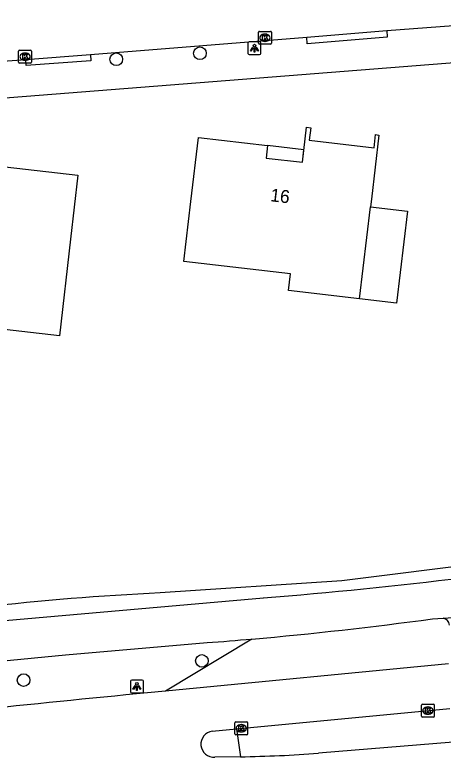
# Model space of a CAD drawing. Extents: x 162398 to 163643, y 386453 to 387397.
# Drawn here: x 163096.1 to 163129.2, y 386513 to 386570.4 of the extents above; entities that cross this region are included whole.
import ezdxf

# ---------------------------------------------------------------- set-up
doc = ezdxf.new("R2010")
doc.units = 0
for name, color, linetype in [('IMGEO_Berm_groen', 7, 'Continuous'), ('IMGEO_Boom', 7, 'Continuous'), ('IMGEO_Fietspad_gesloten', 7, 'Continuous'), ('IMGEO_Groenvoorziening', 7, 'Continuous'), ('IMGEO_Kolk', 7, 'Continuous'), ('IMGEO_Lichtpunt', 7, 'Continuous'), ('IMGEO_Muur', 7, 'Continuous'), ('IMGEO_Pand', 7, 'Continuous'), ('IMGEO_Pand_nummerreeks', 7, 'Continuous'), ('IMGEO_Pand_overbouw', 7, 'Continuous'), ('IMGEO_Rijbaan_lokaal_open', 7, 'Continuous'), ('IMGEO_Rijbaan_regionaal_gesloten', 7, 'Continuous'), ('IMGEO_Verkeerseiland_gesloten', 7, 'Continuous'), ('IMGEO_Voetpad_open', 7, 'Continuous')]:
    doc.layers.add(name, color=color, linetype=linetype)

msp = doc.modelspace()

# ---------------------------------------------------------------- linework, layer by layer
at = {"layer": 'IMGEO_Berm_groen'}
msp.add_lwpolyline([(163114.445, 386522.175), (163107.763, 386518.15)], dxfattribs=at)
at = {"layer": 'IMGEO_Boom'}
for centre in [(163110.437, 386567.457), (163103.966, 386566.988), (163110.583, 386520.488), (163096.797, 386518.996)]:
    msp.add_circle(centre, 0.489, dxfattribs=at)
at = {"layer": 'IMGEO_Fietspad_gesloten'}
for points in [[(163068.381, 386520.901), (163093.275, 386523.436), (163115.339, 386525.357)], [(163128.412, 386523.738), (163129.247, 386523.78)], [(163129.247, 386523.78), (163132.704, 386524.019), (163132.995, 386520.565)], [(163067.923, 386517.561), (163068.628, 386517.907), (163100.034, 386520.946), (163110.988, 386521.896)]]:
    msp.add_lwpolyline(points, dxfattribs=at)
for centre, radius, start, end in [((163086.566, 386887.267), 363.052, 274.54557, 277.00234), ((163089.879, 386804.881), 283.772, 274.96624, 277.80418), ((163090.814, 386793.421), 272.273, 274.24918, 274.97902)]:
    msp.add_arc(centre, radius, start, end, dxfattribs=at)
at = {"layer": 'IMGEO_Groenvoorziening'}
msp.add_lwpolyline([(163243.313, 386542.596), (163241.901, 386539.593), (163239.582, 386537.387), (163183.884, 386534.66), (163132.616, 386530.652), (163132.716, 386528.091), (163121.414, 386526.667), (163107.365, 386525.735)], dxfattribs=at)
msp.add_arc((163115.529, 386339.232), 186.681, 92.50635, 96.74894, dxfattribs=at)
at = {"layer": 'IMGEO_Kolk'}
for p, q in [((163114.965, 386568.225), (163114.965, 386569.077)), ((163115.04, 386569.151), (163115.892, 386569.151)), ((163115.966, 386569.077), (163115.966, 386568.225)), ((163115.453, 386568.931), (163115.478, 386568.931)), ((163115.892, 386568.151), (163115.04, 386568.151)), ((163115.476, 386568.371), (163115.451, 386568.371)), ((163096.409, 386566.77), (163096.409, 386567.622)), ((163096.484, 386567.696), (163097.336, 386567.696)), ((163096.897, 386567.476), (163096.922, 386567.476)), ((163097.41, 386567.622), (163097.41, 386566.77)), ((163097.336, 386566.696), (163096.484, 386566.696)), ((163096.92, 386566.916), (163096.895, 386566.916)), ((163127.563, 386516.218), (163127.563, 386517.07)), ((163127.638, 386517.144), (163128.49, 386517.144)), ((163128.051, 386516.924), (163128.076, 386516.924)), ((163128.564, 386517.07), (163128.564, 386516.218)), ((163128.074, 386516.364), (163128.049, 386516.364)), ((163113.126, 386514.851), (163113.126, 386515.703)), ((163113.201, 386515.777), (163114.053, 386515.777)), ((163114.127, 386515.703), (163114.127, 386514.851)), ((163128.49, 386516.144), (163127.638, 386516.144)), ((163113.614, 386515.557), (163113.639, 386515.557)), ((163114.053, 386514.777), (163113.201, 386514.777)), ((163113.637, 386514.997), (163113.612, 386514.997))]:
    msp.add_line(p, q, dxfattribs=at)
for points in [[(163114.965, 386568.225), (163114.965, 386569.077)], [(163115.04, 386569.151), (163115.892, 386569.151)], [(163115.966, 386569.077), (163115.966, 386568.225)], [(163115.286, 386568.851), (163115.409, 386568.851), (163115.409, 386568.7), (163115.539, 386568.851), (163115.703, 386568.851), (163115.557, 386568.7), (163115.71, 386568.451), (163115.558, 386568.451), (163115.473, 386568.615), (163115.409, 386568.548), (163115.409, 386568.451), (163115.286, 386568.451), (163115.286, 386568.851)], [(163115.892, 386568.151), (163115.04, 386568.151)], [(163096.409, 386566.77), (163096.409, 386567.622)], [(163096.484, 386567.696), (163097.336, 386567.696)], [(163096.73, 386567.396), (163096.853, 386567.396), (163096.853, 386567.245), (163096.983, 386567.396), (163097.147, 386567.396), (163097.001, 386567.245), (163097.154, 386566.996), (163097.002, 386566.996), (163096.917, 386567.16), (163096.853, 386567.093), (163096.853, 386566.996), (163096.73, 386566.996), (163096.73, 386567.396)], [(163097.41, 386567.622), (163097.41, 386566.77)], [(163097.336, 386566.696), (163096.484, 386566.696)], [(163127.563, 386516.218), (163127.563, 386517.07)], [(163127.638, 386517.144), (163128.49, 386517.144)], [(163127.884, 386516.844), (163128.007, 386516.844), (163128.007, 386516.693), (163128.137, 386516.844), (163128.301, 386516.844), (163128.155, 386516.693), (163128.308, 386516.444), (163128.156, 386516.444), (163128.071, 386516.608), (163128.007, 386516.541), (163128.007, 386516.444), (163127.884, 386516.444), (163127.884, 386516.844)], [(163128.564, 386517.07), (163128.564, 386516.218)], [(163113.126, 386514.851), (163113.126, 386515.703)], [(163113.201, 386515.777), (163114.053, 386515.777)], [(163114.127, 386515.703), (163114.127, 386514.851)], [(163128.49, 386516.144), (163127.638, 386516.144)], [(163113.447, 386515.477), (163113.57, 386515.477), (163113.57, 386515.326), (163113.7, 386515.477), (163113.864, 386515.477), (163113.718, 386515.326), (163113.871, 386515.077), (163113.719, 386515.077), (163113.634, 386515.241), (163113.57, 386515.174), (163113.57, 386515.077), (163113.447, 386515.077), (163113.447, 386515.477)], [(163114.053, 386514.777), (163113.201, 386514.777)]]:
    msp.add_lwpolyline(points, dxfattribs=at)
for centre, start, end in [((163115.042, 386569.075), 91.55205, 178.44795), ((163115.042, 386569.075), 91.55205, 178.44795), ((163115.89, 386569.075), 1.55205, 88.44795), ((163115.89, 386569.075), 1.55205, 88.44795), ((163115.042, 386568.227), 181.55205, 268.44795), ((163115.042, 386568.227), 181.55205, 268.44795), ((163115.89, 386568.227), 271.55205, 358.44795), ((163115.89, 386568.227), 271.55205, 358.44795), ((163096.486, 386567.62), 91.55205, 178.44795), ((163096.486, 386567.62), 91.55205, 178.44795), ((163097.334, 386567.62), 1.55205, 88.44795), ((163097.334, 386567.62), 1.55205, 88.44795), ((163096.486, 386566.772), 181.55205, 268.44795), ((163096.486, 386566.772), 181.55205, 268.44795), ((163097.334, 386566.772), 271.55205, 358.44795), ((163097.334, 386566.772), 271.55205, 358.44795), ((163127.64, 386517.068), 91.55205, 178.44795), ((163127.64, 386517.068), 91.55205, 178.44795), ((163128.488, 386517.068), 1.55205, 88.44795), ((163128.488, 386517.068), 1.55205, 88.44795), ((163127.64, 386516.22), 181.55205, 268.44795), ((163127.64, 386516.22), 181.55205, 268.44795), ((163128.488, 386516.22), 271.55205, 358.44795), ((163128.488, 386516.22), 271.55205, 358.44795), ((163113.203, 386515.701), 91.55205, 178.44795), ((163113.203, 386515.701), 91.55205, 178.44795), ((163114.051, 386515.701), 1.55205, 88.44795), ((163114.051, 386515.701), 1.55205, 88.44795), ((163113.203, 386514.853), 181.55205, 268.44795), ((163113.203, 386514.853), 181.55205, 268.44795), ((163114.051, 386514.853), 271.55205, 358.44795), ((163114.051, 386514.853), 271.55205, 358.44795)]:
    msp.add_arc(centre, 0.0765, start, end, dxfattribs=at)
for centre, major_axis, ratio, start_param, end_param in [((163115.452, 386568.651), (-0.387, 0.002), 0.722429, 4.712389, 7.853982), ((163115.477, 386568.651), (-0.39, 0.002), 0.717154, 1.570796, 4.712389), ((163096.896, 386567.196), (-0.387, 0.002), 0.722429, 4.712389, 7.853982), ((163096.921, 386567.196), (-0.39, 0.002), 0.717154, 1.570796, 4.712389), ((163128.05, 386516.644), (-0.387, 0.002), 0.722429, 4.712389, 7.853982), ((163128.075, 386516.644), (-0.39, 0.002), 0.717154, 1.570796, 4.712389), ((163113.613, 386515.277), (-0.387, 0.002), 0.722429, 4.712389, 7.853982), ((163113.638, 386515.277), (-0.39, 0.002), 0.717154, 1.570796, 4.712389)]:
    msp.add_ellipse(centre, major_axis=major_axis, ratio=ratio, start_param=start_param, end_param=end_param, dxfattribs=at)
at = {"layer": 'IMGEO_Lichtpunt'}
for p, q in [((163114.152, 386568.252), (163114.152, 386567.445)), ((163114.152, 386568.252), (163114.152, 386567.445)), ((163115.054, 386568.347), (163114.246, 386568.347)), ((163115.054, 386568.347), (163114.246, 386568.347)), ((163115.148, 386567.445), (163115.148, 386568.252)), ((163115.148, 386567.445), (163115.148, 386568.252)), ((163114.246, 386567.351), (163115.054, 386567.351)), ((163114.246, 386567.351), (163115.054, 386567.351)), ((163105.064, 386518.909), (163105.064, 386518.102)), ((163105.064, 386518.909), (163105.064, 386518.102)), ((163105.966, 386519.004), (163105.158, 386519.004)), ((163105.966, 386519.004), (163105.158, 386519.004)), ((163106.06, 386518.102), (163106.06, 386518.909)), ((163106.06, 386518.102), (163106.06, 386518.909)), ((163105.158, 386518.008), (163105.966, 386518.008)), ((163105.158, 386518.008), (163105.966, 386518.008))]:
    msp.add_line(p, q, dxfattribs=at)
for points in [[(163114.526, 386567.916), (163114.565, 386567.888), (163114.377, 386567.626), (163114.339, 386567.653), (163114.526, 386567.916)], [(163114.628, 386567.868), (163114.675, 386567.868), (163114.675, 386567.546), (163114.628, 386567.546), (163114.628, 386567.868)], [(163114.738, 386567.888), (163114.776, 386567.915), (163114.963, 386567.653), (163114.924, 386567.625), (163114.738, 386567.888)], [(163105.438, 386518.573), (163105.477, 386518.545), (163105.289, 386518.283), (163105.251, 386518.31), (163105.438, 386518.573)], [(163105.54, 386518.525), (163105.587, 386518.525), (163105.587, 386518.203), (163105.54, 386518.203), (163105.54, 386518.525)], [(163105.65, 386518.545), (163105.688, 386518.572), (163105.875, 386518.31), (163105.836, 386518.282), (163105.65, 386518.545)]]:
    msp.add_lwpolyline(points, dxfattribs=at)
for centre in [(163114.651, 386568.05), (163105.563, 386518.707)]:
    msp.add_circle(centre, 0.0994, dxfattribs=at)
for centre, start, end in [((163114.246, 386568.252), 90, 180), ((163114.246, 386568.252), 90, 180), ((163115.054, 386568.252), 0, 90), ((163115.054, 386568.252), 0, 90), ((163114.246, 386567.445), 180, 270), ((163114.246, 386567.445), 180, 270), ((163115.054, 386567.445), 270, 0), ((163115.054, 386567.445), 270, 360), ((163105.158, 386518.909), 90, 180), ((163105.158, 386518.909), 90, 180), ((163105.966, 386518.909), 0, 90), ((163105.966, 386518.909), 0, 90), ((163105.158, 386518.102), 180, 270), ((163105.158, 386518.102), 180, 270), ((163105.966, 386518.102), 270, 0), ((163105.966, 386518.102), 270, 360)]:
    msp.add_arc(centre, 0.0946, start, end, dxfattribs=at)
at = {"layer": 'IMGEO_Muur'}
msp.add_lwpolyline([(163243.313, 386542.596), (163241.901, 386539.593), (163239.582, 386537.387), (163183.884, 386534.66), (163132.616, 386530.652), (163132.716, 386528.091), (163121.414, 386526.667), (163107.365, 386525.735)], dxfattribs=at)
msp.add_arc((163115.529, 386339.232), 186.681, 92.50635, 96.74894, dxfattribs=at)
at = {"layer": 'IMGEO_Pand'}
for points in [[(163122.781, 386548.467), (163117.278, 386549.118), (163117.429, 386550.394), (163109.191, 386551.368), (163109.737, 386555.988), (163110.324, 386560.953), (163115.673, 386560.32), (163115.559, 386559.359), (163118.356, 386559.028), (163118.677, 386561.743), (163119.006, 386561.704), (163118.893, 386560.749), (163123.9, 386560.157), (163124.019, 386561.166), (163124.279, 386561.135), (163123.692, 386556.17), (163123.622, 386555.58)], [(163082.311, 386547.598), (163083.189, 386555.309), (163087.476, 386554.821), (163088.006, 386559.453), (163088.447, 386559.403), (163088.324, 386558.334), (163095.242, 386557.543), (163095.372, 386558.687), (163100.995, 386558.044), (163100.427, 386553.077), (163099.576, 386545.625), (163082.311, 386547.598)], [(163123.622, 386555.58), (163126.49, 386555.241), (163125.648, 386548.128), (163122.781, 386548.467)], [(163122.781, 386548.467), (163123.622, 386555.58)]]:
    msp.add_lwpolyline(points, dxfattribs=at)
at = {"layer": 'IMGEO_Pand_overbouw'}
msp.add_lwpolyline([(163118.469, 386559.989), (163115.673, 386560.32), (163115.559, 386559.359), (163118.356, 386559.028)], close=True, dxfattribs=at)
at = {"layer": 'IMGEO_Rijbaan_lokaal_open'}
for points in [[(163124.883, 386569.21), (163138.986, 386570.276), (163139.978, 386570.426)], [(163118.7, 386568.695), (163124.883, 386569.21)], [(163101.964, 386567.36), (163118.7, 386568.695)], [(163096.974, 386566.98), (163101.964, 386567.36)], [(163087.793, 386566.294), (163096.974, 386566.98)]]:
    msp.add_lwpolyline(points, dxfattribs=at)
at = {"layer": 'IMGEO_Rijbaan_regionaal_gesloten'}
for points in [[(163129.649, 386520.259), (163107.763, 386518.15)], [(163107.763, 386518.15), (163106.385, 386518.017)], [(163113.263, 386515.243), (163129.754, 386516.804)], [(163111.389, 386515.058), (163113.263, 386515.243)], [(163130.019, 386514.208), (163119.609, 386513.357)], [(163113.565, 386513.075), (163111.597, 386513.047)]]:
    msp.add_lwpolyline(points, dxfattribs=at)
for centre, radius, start, end in [((163222.591, 385306.317), 1217.26, 95.478115, 96.758428), ((163111.52, 386514.055), 1.011, 97.43383, 274.37651), ((163112.409, 386602.756), 89.688, 270.73834, 274.60438)]:
    msp.add_arc(centre, radius, start, end, dxfattribs=at)
at = {"layer": 'IMGEO_Verkeerseiland_gesloten'}
msp.add_lwpolyline([(163113.263, 386515.243), (163113.565, 386513.075)], dxfattribs=at)
at = {"layer": 'IMGEO_Voetpad_open'}
for points in [[(163124.883, 386569.21), (163124.919, 386568.712), (163118.736, 386568.197), (163118.7, 386568.695)], [(163139.616, 386567.455), (163000, 386556.492), (162997.872, 386556.325)], [(163101.964, 386567.36), (163102, 386566.862), (163097.009, 386566.501), (163096.974, 386566.98)]]:
    msp.add_lwpolyline(points, dxfattribs=at)
msp.add_arc((163129.182, 386523.239), 0.545, 1.24125, 83.19821, dxfattribs=at)

# ---------------------------------------------------------------- texts
at = {"layer": 'IMGEO_Pand_nummerreeks'}
msp.add_text('16', height=1, rotation=353.25056, dxfattribs=at).set_placement((163115.843, 386556.022))

doc.saveas('drawing.dxf')
